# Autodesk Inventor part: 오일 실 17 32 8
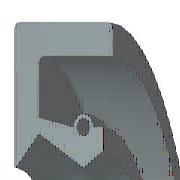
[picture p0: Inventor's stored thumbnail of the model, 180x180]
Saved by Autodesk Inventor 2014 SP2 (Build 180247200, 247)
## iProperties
IsCustomPart: 0
Created: 2018-09
Part Number: 오일 실 17 32 8
Material: 고무
Description: 오일-실
Document SubType Name: Modeling
Standard: KS B 2804
Standards Organization: KS
Language: ko-KR
Size Designation: D - 17 32 8
Categories: <MemberInstance><Categories><Category DisplayName="샤프트 부품" InternalName="7f7aeb1f-a693-4053-b835-cee3144e0d98" Mnemonic="SHFT"><Category DisplayName="실링" Intern
Density: 0.93 g/cm^3
Appearance: 고무 - 검은색 - 버전 1.1
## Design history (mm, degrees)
revolve "본체" stored, may be unused: angle "d17" = 90 deg
revolve "스프링1" stored, may be unused: angle "d18" = 90 deg
body "Solid1"
sketch "스케치1"
  geometry: L1 (0, 16)-(8, 16); L2 (8, 14.25)-(1.75, 14.25); L3 (1.75, 10.25)-(4.9, 8.5); L4 (4.9, 8.5)-(0, 8.5); L5 (0, 0)-(9.586, 0) reference; L6 (4.9, 8.5)-(6.3, 9.375); L7 (0, 18)-(0, -3) reference; L8 (-1.941, 0)-(11.507, 0) reference; L9 (4.2, 10.6)-(1.75, 11.21); L10 (1.75, 11.21)-(1.75, 14.25); L11 (0, 16)-(0, 8.588); L12 (4.9, 8.5)-(0, 8.5); L13 (1.75, 10.25)-(0.152, 8.528); L14 (8, 16)-(8, 14.25); L15 (5.6, 10.6)-(6.3, 10.6); L16 (6.3, 10.6)-(6.3, 9.375); C1 r 0.455 at (4.9, 10.6); A1 r 0.7 centre (4.9, 10.6) between (5.6, 10.6) and (4.2, 10.6); A2 r 0.088 centre (0.088, 8.588) between (0, 8.588) and (0.152, 8.528); 1 further point
  constraints: 28 end point, 5 horizontal alignment, 5 point on line, 4 point on circle, 4 vertical alignment, 3 centre point, 3 tangent, 2 collinear, 2 horizontal, 2 perpendicular, 1 coincident, 1 parallel
  dimensions: "d0" = 32 diameter of L1 L5 (= SD2); "d1" = 1.75 distance of L1.end L2.start (= SD); "d2" = 0.91 diameter of C1 (= SPDI); "d3" = 1.4 diameter of A1 (= SPDA); "d4" = 17 diameter of L3.end L5 (= NND); "d5" = 20.5 diameter of L3.start L5 (= TKDM); "d7" = 22.42 diameter of L9.end L5 (= TKDM + 0.24 x SWDT); "d8" = 1.75 distance between parallel lines of L11 L10 (= SD); "d9" = 4.9 distance from line of L11 C1.centre (= SPDST); "d10" = 21.2 diameter of C1.centre L5 (= HLDM); "d11" = 0.0875 radius of A2 (= 0.25 x LAB); "d12" = 6.3 distance between parallel lines of L11 L16 (= SDI); "d13" = 18.75 diameter of L6.end L5 (= ABDM); "d14" = 8 distance from line of L11 L1.end (= SWDT)
fillet "모깎기1" dims "d6" = 0.3 (= RR)
other parameters: "SD2" = 32 [user parameter; used in 1 equation term], "SWDT" = 8 [user parameter; used in 2 equation terms], "RR" = 0.3 [user parameter; used in 1 equation term], "SD" = 1.75 [user parameter; used in 2 equation terms], "NND" = 17 [user parameter; used in 1 equation term], "SPDA" = 1.4 [user parameter; used in 1 equation term], "SPDI" = 0.91 [user parameter; used in 1 equation term], "TKDM" = 20.5 [user parameter; used in 2 equation terms], "HLDM" = 21.2 [user parameter; used in 1 equation term], "ABDM" = 18.75 [user parameter; used in 1 equation term], "SDI" = 6.3 [user parameter; used in 1 equation term], "SPDST" = 4.9 [user parameter; used in 1 equation term], "LAB" = 0.35 [user parameter; used in 1 equation term], "d15" = 0, "d16" = 0, "d19" = 0
